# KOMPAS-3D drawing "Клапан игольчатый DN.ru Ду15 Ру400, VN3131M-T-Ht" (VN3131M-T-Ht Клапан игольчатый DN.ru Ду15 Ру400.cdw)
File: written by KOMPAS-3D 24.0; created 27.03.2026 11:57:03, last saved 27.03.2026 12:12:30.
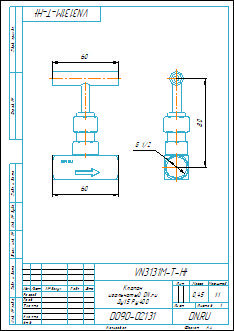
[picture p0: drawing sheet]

Document properties: Автор: Илья; Форматы листов документа: A4; Полное имя файла: VN3131M-T-Ht Клапан игольчатый DN.ru Ду15 Ру400.m3d; Масса: 0.45; Наименование: Клапан игольчатый DN.ru Ду15 Ру400; Количество листов документа: 1; Примечание: D090-02131

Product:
- Body: Body6  | qty 1
    Масса: 0.282571
- Part/product: Клапан игольчатый DN.ru Ду15 Ру400  | designation VN3131M-T-Ht
    Масса: 0.45
    Раздел спецификации: Прочие изделия
    Примечание: D090-02131

Views: Вид 1, Слева, Проекционный вид 2
Referenced files in D:\Обмен\Заказы с фриланса\DN.ru\VNxxM-T-Ht Клапан игольчатый DN.ru Ду8-50 Ру400\VN3232M-T-Ht Клапан игольчатый DN.ru Ду8-50 Ру400\DN8\: VN3232M-T-Ht Клапан игольчатый DN.ru Ду8 Ру400.m3d, VN3232M-T-Ht Клапан игольчатый DN.ru Ду8 Ру400.cdw
Referenced files in D:\Обмен\Заказы с фриланса\DN.ru\VNxxM-T-Ht Клапан игольчатый DN.ru Ду8-50 Ру400\VN3131M-T-Ht Клапан игольчатый DN.ru Ду8-50 Ру400\DN15\: VN3131M-T-Ht Клапан игольчатый DN.ru Ду15 Ру400.m3d
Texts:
  VN3131M-T-Ht
  Клапан
  игольчатый DN.ru
  Ду15 Ру400
  Body6
  Клапан игольчатый DN.ru Ду15 Ру400
  VN3131M-T-Ht Клапан игольчатый DN.ru Ду15 Ру400
Dimensions and other numbers on the sheet: 0; 3; 2; 4; 60; 80; 1:1; 1; 0,45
